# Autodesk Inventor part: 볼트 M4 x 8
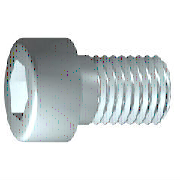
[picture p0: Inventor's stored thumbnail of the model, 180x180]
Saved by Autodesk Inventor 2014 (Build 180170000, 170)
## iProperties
IsCustomPart: 1
Created: 2012-02
Part Number: 볼트 M4 x 8
Material: 스테인리스강
Description: 6각 소켓 머리 캡 나사
Document SubType Name: Modeling
Standard: ISO 4762
Designer: mduedu
Standard Revision: Fourth edition 2004-03-01
Standards Organization: ISO
Language: ko-KR
Size Designation: M4 x 8
Categories: <MemberInstance><Categories><Category DisplayName="조임쇠" InternalName="e4da775c-781d-43d5-af7c-5136215cf5a6" Mnemonic="FSTN"><Category DisplayName="볼트" InternalN
Density: 7.75 g/cm^3
Appearance: 반광택
Author: mduedu
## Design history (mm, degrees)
sketch "스케치1"
  geometry: L1 (-1, 0)-(8, 0); L2 (8, 0)-(8, 2); L3 (8, 2)-(1.75, 2); L4 (1.75, 2)-(1.32, 2); L5 (1.32, 2)-(0, 2); L6 (0, 2)-(0, 3.5); L7 (0, 3.5)-(-4, 3.5); L8 (-4, 3.5)-(-4, 1.732); L9 (-4, 1.732)-(-2, 1.732); L10 (-2, 1.732)-(-1, 0); L11 (-6.4, 0)-(10.4, 0) reference; L12 (0, -0.7)-(0, 4.2) reference; L13 (1.75, 2)-(0, 2)
  constraints: 22 end point, 6 parallel, 2 collinear, 2 perpendicular, 1 horizontal, 1 point on line
  dimensions: "d1" = 6.25 distance from line of L3.end L2 (= GEL); "d2" = 0.42952 distance of L4.end L3.end (computed from GAL); "d3" = 4 distance between parallel lines of L8 L6 (= KOH); "d4" = 2 distance of L8.end L9.end (= INTI); "d5" = 60 deg angle of L10 L1; "d6" = 4 diameter of L3 L1 (= GD); "d7" = 4 diameter of L5 L1 (= BDM); "d8" = 3.4641 diameter of L9 L1 (= 1.1547 x SW); "d9" = 7 diameter of L7 L1 (= KOD); "d26" = 8 distance between parallel lines of L12 L2 (= NLG)
revolve "본체" sketch "스케치1" stored, may be unused: angle "d10" = 90 deg
sketch "스케치2"
  geometry: L1 (0, -4.9)-(0, 4.9) reference; L2 (-4.9, 0)-(4.9, 0) reference; L3 (1.732, 0)-(0.866, -1.5); L4 (0.866, -1.5)-(-0.866, -1.5); L5 (-0.866, -1.5)-(-1.732, 0); L6 (-1.732, 0)-(-0.866, 1.5); L7 (-0.866, 1.5)-(0.866, 1.5); L8 (0.866, 1.5)-(1.732, 0); 2 further points
  constraints: 12 end point, 1 coincident, 1 horizontal alignment, 1 point on line, 12 other
extrude "슬롯" join sketch "스케치2" stored distance "d11" = 10; taper "d12" = 0 deg
workplane "Work Plane1"
fillet "Fillet2" dims "d30" = 0.1 (= R)
body "Solid1"
fillet "모깎기1" dims "d17" = 0.4 (= RR)
feature "스레드" dims "d13" = 6.25 (= GEL), "d14" = 0
chamfer "모따기1" distance "d15" = 0.42941 (= -0.5 x SPD + 0.5 x GD); stored, may be unused: second distance "d16" = 0.42941 (= GUL), angle "d27" = 45 deg
other parameters: "GD" = 4 [user parameter; used in 2 equation terms], "NLG" = 8 [user parameter; used in 1 equation term], "GEL" = 6.25 [user parameter; used in 2 equation terms], "KOD" = 7 [user parameter; used in 1 equation term], "KOH" = 4 [user parameter; used in 1 equation term], "INTI" = 2 [user parameter; used in 1 equation term], "GAL" = 0.42941 (= 0.61345 x PTC) [user parameter; used in 1 equation term], "GUL" = 0.42941 (= 0.61345 x PTC) [user parameter; used in 1 equation term], "BDM" = 4 (= NND) [user parameter; used in 1 equation term], "SW" = 3 [user parameter; used in 2 equation terms], "RR" = 0.4 [user parameter; used in 1 equation term], "SPD" = 3.14117 (= NND - 1.2269 x PTC) [user parameter; used in 1 equation term], "d19" = 0, "d28" = 0, "d29" = 0, "R" = 0.1 [user parameter; used in 1 equation term], "TOA" = 30 deg [user parameter], "GD1" = 3.14117 (= THREADDIA - 1.2269 x PTC) [user parameter], "THREADDIA" = 4 [user parameter; used in 1 equation term], "FAWI" = 45 deg [user parameter], "TPU" = 14.28571 (computed from PTC) [user parameter], "PTC" = 0.7 [user parameter; used in 5 equation terms], "NND" = 4 [user parameter; used in 2 equation terms], "E0" = 3.465 (= 1.155 x SW) [user parameter]
